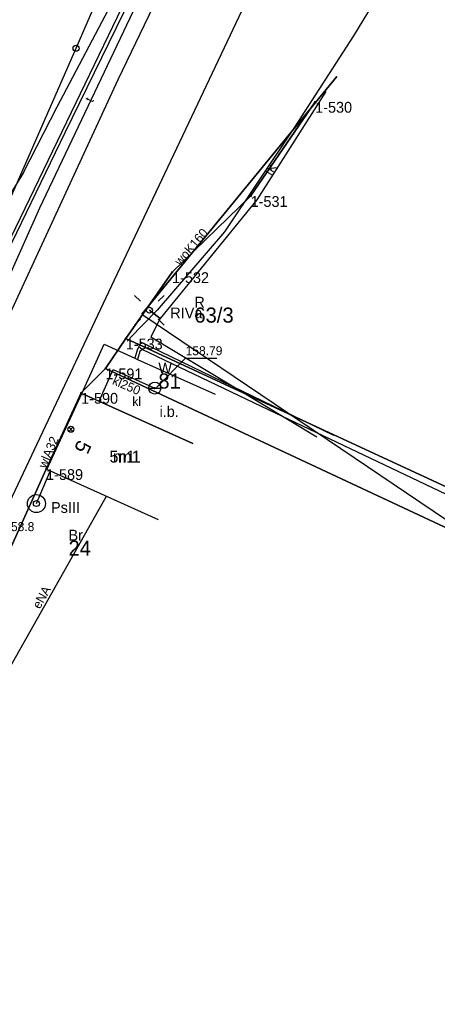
# Model space of a CAD drawing. Extents: x 5598798 to 5599616, y 5661498 to 5662453.
# Drawn here: x 5599153.6 to 5599188.5, y 5661640 to 5661721.5 of the extents above; entities that cross this region are included whole.
import ezdxf

# ---------------------------------------------------------------- set-up
doc = ezdxf.new("R2010")
doc.units = 0
for name, color, linetype in [('BUIB_E_T_6', 7, 'Continuous'), ('BUIB_L_10', 7, 'Continuous'), ('Dzialki', 7, 'Continuous'), ('EADTD_T_0', 7, 'Continuous'), ('EAPADR_T_0', 7, 'Continuous'), ('EGBB_E_T_0', 7, 'Continuous'), ('EGBB_E_T_1', 7, 'Continuous'), ('EGBB_L_0', 7, 'Continuous'), ('Kontury', 7, 'Continuous'), ('KTJZ_L_0', 7, 'Continuous'), ('KTOK_L_1', 7, 'Continuous'), ('KTOK_L_4', 7, 'Continuous'), ('KTPL_L_0', 7, 'Continuous'), ('Numery_dzialek', 7, 'Continuous'), ('Numery_konturow', 7, 'Continuous'), ('Numery_punktow', 7, 'Continuous'), ('Numery_uzytkow', 7, 'Continuous'), ('Punkty', 7, 'Continuous'), ('RTPW_T_0', 7, 'Continuous'), ('SUPE_E_T_3', 7, 'Continuous'), ('SUPE_L_3', 7, 'Continuous'), ('SUPK_E_T_1', 7, 'Continuous'), ('SUPK_L_1', 7, 'Continuous'), ('SUPT_E_T_0', 7, 'Continuous'), ('SUPT_L_0', 7, 'Continuous'), ('SUPW_E_T_0', 7, 'Continuous'), ('SUPW_E_T_1', 7, 'Continuous'), ('SUPW_L_0', 7, 'Continuous'), ('SUPW_L_1', 7, 'Continuous'), ('SUSM_T_0', 7, 'Continuous'), ('SUSM_T_3', 7, 'Continuous'), ('SUTK_T_0', 7, 'Continuous'), ('SUUK_E_T_1', 7, 'Continuous'), ('SUUK_T_1', 7, 'Continuous'), ('SUUW_T_1', 7, 'Continuous'), ('Uzytki', 7, 'Continuous')]:
    doc.layers.add(name, color=color, linetype=linetype)

# ---------------------------------------------------------------- blocks, each defined once
blk = doc.blocks.new('GRO')
blk.add_circle((0, 0), 0.045)
blk = doc.blocks.new('1_PADR')
for p, q in [((-0.17675, -0.17675), (0.17675, 0.17675)), ((0.17675, -0.17675), (-0.17675, 0.17675))]:
    blk.add_line(p, q)
blk.add_circle((0, 0), 0.25)
blk = doc.blocks.new('4_SUSM04_01')
blk.add_circle((0, 0), 0.25)
blk = doc.blocks.new('4_SUSM01')
for p, q in [((-0.74249, 0.74249), (-1.23746, 1.23746)), ((0.74249, 0.74249), (1.23746, 1.23746)), ((-0.74249, -0.74249), (-1.23746, -1.23746)), ((0.74249, -0.74249), (1.23746, -1.23746))]:
    blk.add_line(p, q)
blk.add_circle((0, 0), 0.245)
blk = doc.blocks.new('4_SUPS01_05')
blk.add_circle((0, 0), 0.0625)
blk = doc.blocks.new('4_SUUS07')
blk.add_line((-0.5, 0), (0.5, 0))
blk.add_circle((0, 0), 0.5)
blk = doc.blocks.new('4_SUUS13')
for radius in [0.75, 0.25]:
    blk.add_circle((0, 0), radius)

msp = doc.modelspace()

# ---------------------------------------------------------------- linework, layer by layer
at = {"layer": 'BUIB_L_10'}
for p, q in [((5599158.81, 5661690.27), (5599160.69, 5661694.37)), ((5599160.69, 5661694.37), (5599163.24, 5661693.22)), ((5599163.24, 5661693.22), (5599163.47, 5661693.11)), ((5599163.47, 5661693.11), (5599169.93, 5661690.2)), ((5599168.08, 5661686.1), (5599158.81, 5661690.27))]:
    msp.add_line(p, q, dxfattribs=at)
at = {"layer": 'Dzialki'}
for p, q in [((5599148.41, 5661693.96), (5599172.35, 5661743.59)), ((5599178.27, 5661714.59), (5599172.89, 5661706.73)), ((5599172.89, 5661706.73), (5599166.34, 5661700.38)), ((5599166.34, 5661700.38), (5599162.48, 5661694.84)), ((5599162.48, 5661694.84), (5599160.79, 5661692.35)), ((5599206.16, 5661674.62), (5599162.48, 5661694.84)), ((5599160.79, 5661692.35), (5599158.76, 5661690.31)), ((5599202.11, 5661673), (5599160.79, 5661692.35)), ((5599158.76, 5661690.31), (5599155.84, 5661683.95)), ((5599155.84, 5661683.95), (5599136.04, 5661640.04))]:
    msp.add_line(p, q, dxfattribs=at)
at = {"layer": 'EGBB_L_0'}
for p, q in [((5599155.89, 5661683.91), (5599158.81, 5661690.27)), ((5599158.81, 5661690.27), (5599168.08, 5661686.1)), ((5599165.2, 5661679.71), (5599155.89, 5661683.91))]:
    msp.add_line(p, q, dxfattribs=at)
at = {"layer": 'Kontury'}
for p, q in [((5599148.41, 5661693.96), (5599172.35, 5661743.59)), ((5599172.89, 5661706.73), (5599178.27, 5661714.59)), ((5599166.34, 5661700.38), (5599172.89, 5661706.73)), ((5599162.48, 5661694.84), (5599166.34, 5661700.38)), ((5599160.79, 5661692.35), (5599162.48, 5661694.84)), ((5599206.17, 5661674.62), (5599162.48, 5661694.84)), ((5599158.76, 5661690.31), (5599160.79, 5661692.35)), ((5599155.84, 5661683.95), (5599158.76, 5661690.31)), ((5599136.04, 5661640.04), (5599155.84, 5661683.95))]:
    msp.add_line(p, q, dxfattribs=at)
at = {"layer": 'KTJZ_L_0'}
for p, q in [((5599167.19, 5661727.62), (5599161.82, 5661716.42)), ((5599161.53, 5661699.74), (5599173.74, 5661725.53)), ((5599161.82, 5661716.42), (5599152.64, 5661696.54)), ((5599152.13, 5661679.75), (5599161.53, 5661699.74))]:
    msp.add_line(p, q, dxfattribs=at)
at = {"layer": 'KTOK_L_1'}
msp.add_line((5599153.946801, 5661708.707327), (5599156.768812, 5661714.174973), dxfattribs=at)
at = {"layer": 'KTOK_L_4'}
for p, q in [((5599156.768812, 5661714.174973), (5599167.170567, 5661734.000977)), ((5599163.81, 5661696.88), (5599180.08, 5661716.71)), ((5599153.946801, 5661708.707327), (5599150.463381, 5661703.019211))]:
    msp.add_line(p, q, dxfattribs=at)
at = {"layer": 'KTPL_L_0'}
for p, q in [((5599180.08, 5661716.71), (5599163.81, 5661696.88)), ((5599163.81, 5661696.88), (5599201.36, 5661671.51))]:
    msp.add_line(p, q, dxfattribs=at)
at = {"layer": 'SUPE_L_3'}
for p, q in [((5599158.332094, 5661719.064332), (5599172.421291, 5661751.519683)), ((5599148.021884, 5661695.534034), (5599158.332094, 5661719.064332)), ((5599179.15, 5661715.45), (5599173.4, 5661706.41)), ((5599173.4, 5661706.41), (5599165.36, 5661696.53)), ((5599164.45, 5661697.21), (5599165.36, 5661696.53)), ((5599165.36, 5661696.53), (5599164.56, 5661695)), ((5599164.56, 5661695), (5599178.42, 5661686.66)), ((5599160.846586, 5661681.673946), (5599149.92, 5661662.3))]:
    msp.add_line(p, q, dxfattribs=at)
at = {"layer": 'SUPK_L_1'}
for p, q in [((5599163.66, 5661693.78), (5599163.47, 5661693.11)), ((5599163.66, 5661693.78), (5599163.47, 5661693.11)), ((5599163.86, 5661693.92), (5599163.66, 5661693.78)), ((5599163.86, 5661693.92), (5599163.66, 5661693.78)), ((5599174.39, 5661688.91), (5599163.86, 5661693.92)), ((5599174.39, 5661688.91), (5599163.86, 5661693.92)), ((5599160.25, 5661689.62), (5599161.44, 5661692.27)), ((5599160.25, 5661689.62), (5599161.44, 5661692.27)), ((5599161.44, 5661692.27), (5599164.9, 5661690.71)), ((5599161.44, 5661692.27), (5599164.9, 5661690.71)), ((5599211.26, 5661671.34), (5599174.39, 5661688.91))]:
    msp.add_line(p, q, dxfattribs=at)
at = {"layer": 'SUPT_L_0'}
for p, q in [((5599157.421027, 5661712.050333), (5599172.422232, 5661742.67554)), ((5599155.313425, 5661705.739483), (5599166.67415, 5661729.708853)), ((5599179.15, 5661715.45), (5599173.4, 5661706.41)), ((5599149.624419, 5661695.89561), (5599157.421027, 5661712.050333)), ((5599142.364839, 5661676.801704), (5599155.313425, 5661705.739483)), ((5599173.4, 5661706.41), (5599165.36, 5661696.53)), ((5599165.36, 5661696.53), (5599164.45, 5661697.21)), ((5599165.36, 5661696.53), (5599164.56, 5661695)), ((5599164.56, 5661695), (5599178.42, 5661686.66))]:
    msp.add_line(p, q, dxfattribs=at)
at = {"layer": 'SUPW_L_0'}
for p, q in [((5599185.42, 5661726.64), (5599181.47, 5661720.11)), ((5599181.47, 5661720.11), (5599176.56, 5661712.47)), ((5599176.56, 5661712.47), (5599170.7, 5661703.74)), ((5599176.56, 5661712.47), (5599170.7, 5661703.74)), ((5599170.7, 5661703.74), (5599165.11, 5661697.21)), ((5599170.7, 5661703.74), (5599165.11, 5661697.21)), ((5599165.11, 5661697.21), (5599162.78, 5661694.86)), ((5599165.11, 5661697.21), (5599162.78, 5661694.86)), ((5599163.74, 5661694.55), (5599163.44, 5661693.89)), ((5599163.74, 5661694.55), (5599163.44, 5661693.89)), ((5599179.82, 5661686.75), (5599163.74, 5661694.55)), ((5599179.82, 5661686.75), (5599163.74, 5661694.55)), ((5599163.44, 5661693.89), (5599163.24, 5661693.22)), ((5599163.44, 5661693.89), (5599163.24, 5661693.22))]:
    msp.add_line(p, q, dxfattribs=at)
at = {"layer": 'SUPW_L_1'}
msp.add_line((5599155.03, 5661681.08), (5599156.176144, 5661683.780913), dxfattribs=at)
at = {"layer": 'SUTK_T_0'}
for p, q in [((5599165.038223, 5661690.775112), (5599167.471039, 5661693.205715)), ((5599167.471039, 5661693.205715), (5599170.076734, 5661693.205715))]:
    msp.add_line(p, q, dxfattribs=at)
at = {"layer": 'Uzytki'}
for p, q in [((5599148.41, 5661693.96), (5599172.35, 5661743.59)), ((5599178.27, 5661714.59), (5599172.89, 5661706.73)), ((5599172.89, 5661706.73), (5599166.34, 5661700.38)), ((5599166.34, 5661700.38), (5599162.48, 5661694.84)), ((5599162.48, 5661694.84), (5599160.79, 5661692.35)), ((5599162.48, 5661694.84), (5599206.17, 5661674.62)), ((5599160.79, 5661692.35), (5599158.76, 5661690.31)), ((5599160.79, 5661692.35), (5599202.11, 5661673)), ((5599158.76, 5661690.31), (5599155.84, 5661683.95)), ((5599155.84, 5661683.95), (5599136.04, 5661640.04))]:
    msp.add_line(p, q, dxfattribs=at)

# ---------------------------------------------------------------- block references
at = {"layer": 'EAPADR_T_0'}
msp.add_blockref('1_PADR', (5599157.901482, 5661687.276991), dxfattribs=at)
at = {"layer": 'Punkty'}
for p in [(5599178.27, 5661714.59), (5599172.89, 5661706.73), (5599166.34, 5661700.38), (5599162.48, 5661694.84), (5599160.79, 5661692.35), (5599158.76, 5661690.31), (5599155.84, 5661683.95)]:
    msp.add_blockref('GRO', p, dxfattribs=at)
at = {"layer": 'SUSM_T_0'}
msp.add_blockref('4_SUSM01', (5599164.45, 5661697.21), dxfattribs=at)
at = {"layer": 'SUSM_T_3'}
msp.add_blockref('4_SUSM04_01', (5599158.332094, 5661719.064332), dxfattribs=at)
at = {"layer": 'SUTK_T_0'}
msp.add_blockref('4_SUPS01_05', (5599164.9, 5661690.71), dxfattribs=at)
at = {"layer": 'SUUK_T_1'}
msp.add_blockref('4_SUUS07', (5599164.9, 5661690.71), dxfattribs=at)
at = {"layer": 'SUUW_T_1'}
msp.add_blockref('4_SUUS13', (5599155.03, 5661681.08), dxfattribs=at)

# ---------------------------------------------------------------- texts
at = {"layer": 'BUIB_E_T_6'}
msp.add_text('i.b.', height=0.9, dxfattribs=at).set_placement((5599165.29629, 5661688.311974))
at = {"layer": 'EADTD_T_0'}
msp.add_text('5', height=1.25, rotation=245.432832, dxfattribs=at).set_placement((5599158.530371, 5661686.468884))
at = {"layer": 'EGBB_E_T_0'}
msp.add_text('m1', height=1, dxfattribs=at).set_placement((5599161.405396, 5661684.4975))
at = {"layer": 'EGBB_E_T_1'}
msp.add_text('5m1', height=1, dxfattribs=at).set_placement((5599161.1238, 5661684.4975))
at = {"layer": 'Numery_dzialek'}
for s, p in [('63/3', (5599168.195703, 5661696.174409)), ('81', (5599165.196043, 5661690.676501)), ('24', (5599157.70867, 5661676.736133))]:
    msp.add_text(s, height=1.26, dxfattribs=at).set_placement(p)
at = {"layer": 'Numery_konturow'}
for s, p in [('RIVa', (5599166.191986, 5661696.534644)), ('PsIII', (5599156.249919, 5661680.304831))]:
    msp.add_text(s, height=0.9, dxfattribs=at).set_placement(p)
at = {"layer": 'Numery_punktow'}
for s, p in [('1-530', (5599178.27, 5661713.69)), ('1-531', (5599172.89, 5661705.83)), ('1-532', (5599166.34, 5661699.48)), ('1-533', (5599162.48, 5661693.94)), ('1-591', (5599160.79, 5661691.45)), ('1-590', (5599158.76, 5661689.41)), ('1-589', (5599155.84, 5661683.05))]:
    msp.add_text(s, height=0.9, dxfattribs=at).set_placement(p)
at = {"layer": 'Numery_uzytkow'}
for s, p in [('R', (5599168.195746, 5661697.434644)), ('W', (5599165.196097, 5661691.936655)), ('Br', (5599157.70867, 5661677.996133))]:
    msp.add_text(s, height=0.9, dxfattribs=at).set_placement(p)
at = {"layer": 'RTPW_T_0'}
msp.add_text('158.8', height=0.75, dxfattribs=at).set_placement((5599152.35, 5661678.78))
at = {"layer": 'SUPE_E_T_3'}
msp.add_text('eNA', height=0.75, rotation=60.57773, dxfattribs=at).set_placement((5599155.309323, 5661672.230699))
at = {"layer": 'SUPK_E_T_1'}
msp.add_text('kl250', height=0.75, rotation=336.56, dxfattribs=at).set_placement((5599161.300048, 5661691.067578))
at = {"layer": 'SUPT_E_T_0'}
for s, rotation, p in [('t', 64.640518, (5599159.719696, 5661714.488492)), ('tK', 57.828879, (5599174.658264, 5661708.361745))]:
    msp.add_text(s, height=0.75, rotation=rotation, dxfattribs=at).set_placement(p)
at = {"layer": 'SUPW_E_T_0'}
msp.add_text('woK160', height=0.75, rotation=49.43485, dxfattribs=at).set_placement((5599167.039666, 5661700.872973))
at = {"layer": 'SUPW_E_T_1'}
msp.add_text('wlA32', height=0.75, rotation=67.005867, dxfattribs=at).set_placement((5599155.835984, 5661683.957464))
at = {"layer": 'SUTK_T_0'}
msp.add_text('158.79', height=0.75, dxfattribs=at).set_placement((5599167.471039, 5661693.455715))
at = {"layer": 'SUUK_E_T_1'}
msp.add_text('kl', height=0.75, dxfattribs=at).set_placement((5599163.028121, 5661689.230354))

doc.saveas('drawing.dxf')
